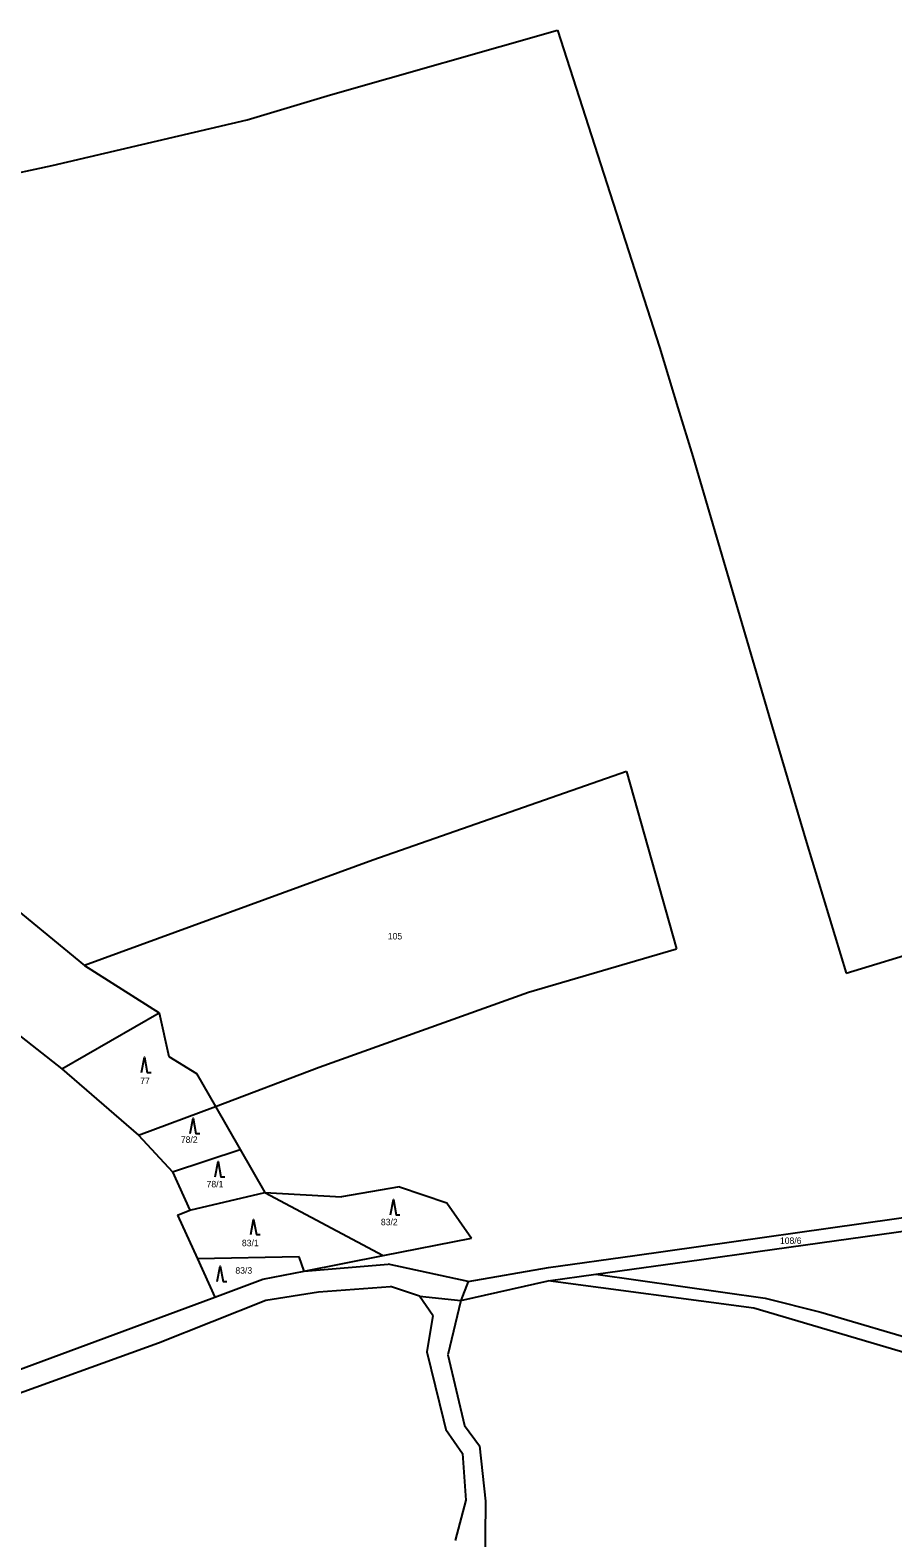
# Model space of a CAD drawing. Extents: x -779723 to -777378, y -1011169 to -1009297.
# Drawn here: x -778656.8 to -778429.5, y -1010110.5 to -1009713.3 of the extents above; entities that cross this region are included whole.
import ezdxf

# ---------------------------------------------------------------- set-up
doc = ezdxf.new("R2010")
doc.units = 0
for name, color, linetype in [('Default', 7, 'Continuous'), ('KN_HRANICE', 7, 'Continuous'), ('KN_KULTURY', 7, 'Continuous'), ('KN_PARCELY', 7, 'Continuous')]:
    doc.layers.add(name, color=color, linetype=linetype)

# ---------------------------------------------------------------- blocks, each defined once
blk = doc.blocks.new('308')
at = {"layer": 'Default'}
blk.add_lwpolyline([(-0.75, 0), (0, 4), (0.75, 0), (1.75, 0)], dxfattribs=at)

msp = doc.modelspace()

# ---------------------------------------------------------------- linework, layer by layer
at = {"layer": 'KN_HRANICE'}
for p, q in [((-778577.68, -1009730.31), (-778517.87, -1009713.29)), ((-778517.87, -1009713.29), (-778491.03, -1009796.82)), ((-778599.62, -1009736.93), (-778577.68, -1009730.31)), ((-778650.92, -1009748.98), (-778599.62, -1009736.93)), ((-778682.79, -1009755.72), (-778650.92, -1009748.98)), ((-778491.03, -1009796.82), (-778486.17, -1009812.8)), ((-778486.17, -1009812.8), (-778482.26, -1009825.63)), ((-778482.26, -1009825.63), (-778477.95, -1009840.27)), ((-778477.95, -1009840.27), (-778461.29, -1009896.85)), ((-778461.29, -1009896.85), (-778452.32, -1009927.34)), ((-778499.66, -1009908.62), (-778566.52, -1009931.95)), ((-778499.66, -1009908.62), (-778486.49, -1009955.32)), ((-778452.32, -1009927.34), (-778441.85, -1009961.74)), ((-778566.52, -1009931.95), (-778642.47, -1009959.73)), ((-778670.88, -1009936.37), (-778642.47, -1009959.73)), ((-778441.85, -1009961.74), (-778409.93, -1009951.93)), ((-778525.48, -1009966.76), (-778486.49, -1009955.32)), ((-778642.47, -1009959.73), (-778622.81, -1009972.22)), ((-778580.61, -1009986.47), (-778525.48, -1009966.76)), ((-778670.06, -1009969.95), (-778648.43, -1009986.95)), ((-778648.43, -1009986.95), (-778622.81, -1009972.22)), ((-778622.81, -1009972.22), (-778620.25, -1009983.66)), ((-778620.25, -1009983.66), (-778612.91, -1009988.16)), ((-778648.43, -1009986.95), (-778628.19, -1010004.45)), ((-778612.91, -1009988.16), (-778607.95, -1009996.84)), ((-778607.95, -1009996.84), (-778580.61, -1009986.47)), ((-778628.19, -1010004.45), (-778607.95, -1009996.84)), ((-778607.95, -1009996.84), (-778601.46, -1010008.2)), ((-778628.19, -1010004.45), (-778619.27, -1010014.08)), ((-778619.27, -1010014.08), (-778601.46, -1010008.2)), ((-778601.46, -1010008.2), (-778594.98, -1010019.53)), ((-778619.27, -1010014.08), (-778614.73, -1010024.15)), ((-778497.51, -1010036.07), (-778348.28, -1010015.11)), ((-778614.73, -1010024.15), (-778594.98, -1010019.53)), ((-778594.98, -1010019.53), (-778574.79, -1010020.66)), ((-778594.98, -1010019.53), (-778563.77, -1010036.13)), ((-778559.52, -1010017.99), (-778574.79, -1010020.66)), ((-778559.52, -1010017.99), (-778547, -1010022.25)), ((-778465.13, -1010035.06), (-778347.45, -1010018.54)), ((-778617.96, -1010025.49), (-778614.73, -1010024.15)), ((-778547, -1010022.25), (-778540.53, -1010031.53)), ((-778617.96, -1010025.49), (-778612.72, -1010037)), ((-778563.77, -1010036.13), (-778540.53, -1010031.53)), ((-778585.92, -1010036.44), (-778612.72, -1010037)), ((-778584.59, -1010040.25), (-778585.92, -1010036.44)), ((-778584.59, -1010040.25), (-778563.77, -1010036.13)), ((-778520.25, -1010039.26), (-778497.51, -1010036.07)), ((-778479.97, -1010037.14), (-778465.13, -1010035.06)), ((-778612.72, -1010037), (-778608.15, -1010047.05)), ((-778595.49, -1010042.35), (-778584.59, -1010040.25)), ((-778584.59, -1010040.25), (-778562.47, -1010038.37)), ((-778541.4, -1010042.99), (-778562.47, -1010038.37)), ((-778541.4, -1010042.99), (-778520.25, -1010039.26)), ((-778507.76, -1010041.04), (-778479.97, -1010037.14)), ((-778608.15, -1010047.05), (-778595.49, -1010042.35)), ((-778580.85, -1010045.72), (-778561.81, -1010044.31)), ((-778554.23, -1010046.82), (-778561.81, -1010044.31)), ((-778543.3, -1010047.94), (-778520.34, -1010042.8)), ((-778541.4, -1010042.99), (-778543.3, -1010047.94)), ((-778520.34, -1010042.8), (-778507.76, -1010041.04)), ((-778466.13, -1010049.97), (-778520.34, -1010042.8)), ((-778507.76, -1010041.04), (-778463.16, -1010047.36)), ((-778695.97, -1010079.62), (-778608.15, -1010047.05)), ((-778622.94, -1010059.11), (-778594.64, -1010047.86)), ((-778594.64, -1010047.86), (-778580.85, -1010045.72)), ((-778550.67, -1010051.95), (-778554.23, -1010046.82)), ((-778554.23, -1010046.82), (-778543.3, -1010047.94)), ((-778543.3, -1010047.94), (-778546.71, -1010062.28)), ((-778463.16, -1010047.36), (-778448.54, -1010051.05)), ((-778550.67, -1010051.95), (-778552.26, -1010061.45)), ((-778423.7, -1010062.57), (-778466.13, -1010049.97)), ((-778448.54, -1010051.05), (-778413.41, -1010061.34)), ((-778684.92, -1010081.46), (-778622.94, -1010059.11)), ((-778552.26, -1010061.45), (-778547.93, -1010079.4)), ((-778546.71, -1010062.28), (-778542.32, -1010080.9)), ((-778547.93, -1010079.4), (-778547.31, -1010081.95)), ((-778547.31, -1010081.95), (-778542.87, -1010088.3)), ((-778542.32, -1010080.9), (-778538.43, -1010086.26)), ((-778542.87, -1010088.3), (-778541.98, -1010100.57)), ((-778538.43, -1010086.26), (-778536.83, -1010100.87)), ((-778541.98, -1010100.57), (-778544.84, -1010111.19)), ((-778536.83, -1010100.87), (-778537.2, -1010135.97))]:
    msp.add_line(p, q, dxfattribs=at)

# ---------------------------------------------------------------- block references
at = {"layer": 'KN_KULTURY'}
for p in [(-778626.66, -1009987.86), (-778613.84, -1010003.94), (-778607.26, -1010015.36), (-778561.1, -1010025.37), (-778597.9, -1010030.61), (-778606.71, -1010042.92)]:
    msp.add_blockref('308', p, dxfattribs=at)

# ---------------------------------------------------------------- texts
at = {"layer": 'KN_PARCELY'}
for s, p in [('105', (-778562.56, -1009952.85)), ('77', (-778627.77, -1009990.93)), ('78/2', (-778617.07, -1010006.44)), ('78/1', (-778610.29, -1010018.15)), ('83/2', (-778564.38, -1010028.14)), ('83/1', (-778600.99, -1010033.66)), ('108/6', (-778459.28, -1010033.06)), ('83/3', (-778602.7, -1010040.89))]:
    msp.add_text(s, height=1.7, dxfattribs=at).set_placement(p)

doc.saveas('drawing.dxf')
